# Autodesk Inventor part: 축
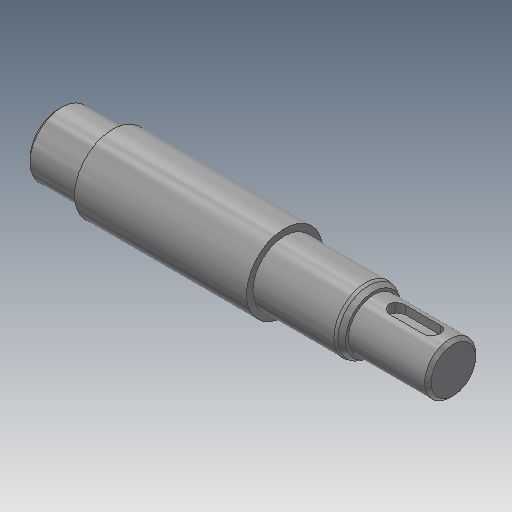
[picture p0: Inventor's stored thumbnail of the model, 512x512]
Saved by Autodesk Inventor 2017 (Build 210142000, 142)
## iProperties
Created: 2016-06
Part Number: 축
Material: 강철, 연강
Document SubType Name: Modeling
Designer: mduedu
Density: 7.86 g/cm^3
Appearance: 강철
Author: mduedu
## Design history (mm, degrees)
sketch "스케치1"
  geometry: L1 (-62, 0)-(62, 0); L2 (-62, 0)-(-62, 10); L3 (-62, 10)-(-45, 10); L4 (-45, 10)-(-45, 12); L5 (-45, 12)-(9, 12); L6 (9, 12)-(9, 10); L7 (9, 10)-(37, 10); L8 (37, 10)-(37, 8); L9 (37, 8)-(62, 8); L10 (62, 8)-(62, 0); 2 further points
  constraints: 20 end point, 5 parallel, 2 perpendicular, 1 coincident, 1 collinear, 1 horizontal, 1 midpoint, 1 vertical
  dimensions: "d0" = 124 distance of L1.start L1.end; "d2" = 16 diameter of L9 L1; "d3" = 20 diameter of L7 L1; "d4" = 24 diameter of L5 L1; "d5" = 20 diameter of L3 L1; "d6" = 17 distance of L2.end L3.end; "d7" = 25 distance of L8.end L9.end; "d8" = 53 distance from line of L5.end L10
revolve "회전1" sketch "스케치1" stored, may be unused: angle "d9" = 90 deg
chamfer "모따기1" distance "d10" = 2; stored, may be unused: second distance "d11" = 2, angle "d12" = 30 deg
fillet "모깎기1" dims "d13" = 2
node "작업 평면1"
sketch "스케치2"
  geometry: L1 (-5, 2.5)-(6, 2.5); L2 (6, -2.5)-(-5, -2.5); L3 (-5, 0)-(6, 0); L4 (-12.5, 8.845)-(-12.5, -8.845) reference; A1 r 2.5 centre (-5, 0) between (-5, 2.5) and (-5, -2.5); A2 r 2.5 centre (6, 0) between (6, -2.5) and (6, 2.5); 1 further point
  constraints: 6 end point, 4 point on circle, 3 tangent, 2 centre point, 2 parallel, 1 horizontal, 1 horizontal alignment
  dimensions: "d14" = 5 distance edge to line of A1 L4; "d15" = 5 distance between parallel lines of L2 L1; "d16" = 16 dimension on A2 A1
extrude "돌출1" cut sketch "스케치2" distance "d17" = 3; taper "d18" = 0 deg
chamfer "모따기2" distance "d19" = 1; stored, may be unused: second distance "d20" = 2, angle "d21" = 30 deg
sketch "스케치3"
  geometry: L1 (-37, -8)-(-61, -8) reference; L2 (-62, -7)-(-62, 7) reference; L3 (-38.5, -8)-(-40, -6.5); L4 (-40, -6.5)-(-40, -8); L5 (-38.5, -8)-(-40, -8); 1 further point
  constraints: 6 end point, 2 point on line, 1 collinear, 1 vertical
  dimensions: "d22" = 45 deg angle of L4 L3; "d23" = 22 distance between parallel lines of L2 L4; "d24" = 3 diameter of L3.start L4
revolve "회전2" stored, may be unused: angle "d25" = 90 deg
node "작업점1"
sketch "스케치4"
  geometry: 1 further point
hole "구멍1" sketch "스케치4" at (0, 0) diameter "d26" = 3.242; stored, may be unused: countersink angle "d30" = 90 deg, drill point angle "d32" = 120 deg; dims "d27" = 8, "d28" = 4, "d29" = 2, "d31" = 11
chamfer "모따기3" distance "d33" = 2; stored, may be unused: second distance "d34" = 2, angle "d35" = 30 deg
node "솔리드1"
